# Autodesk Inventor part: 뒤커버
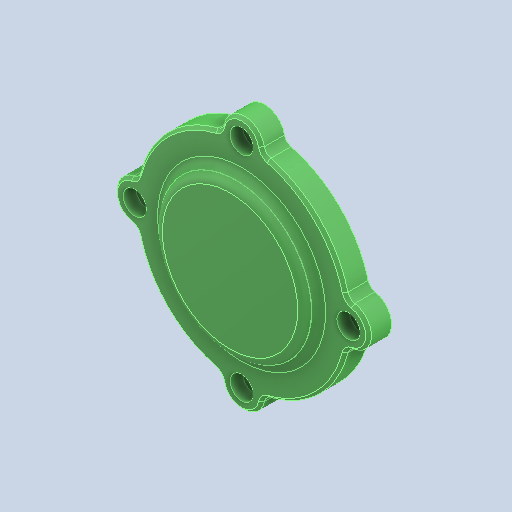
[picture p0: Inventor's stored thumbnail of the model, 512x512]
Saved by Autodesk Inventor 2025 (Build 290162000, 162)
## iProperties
Created: 2025-08
Part Number: 뒤커버
Material: 알루미늄 6061
Document SubType Name: Modeling
Designer: infra02
Density: 2.71 g/cm^3
Appearance: 기본값
Company: 한국ATC센터
Author: jhkim
Sending System: Autodesk Inventor 2026
Preprocessor: ST-DEVELOPER v20.1
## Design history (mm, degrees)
feature "솔리드1"
node "솔리드2"
